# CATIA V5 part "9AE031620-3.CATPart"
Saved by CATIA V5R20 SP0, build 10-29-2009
Part number: 9AE031620-3
Revision: ANY
Definition: UNKNOWN
Nomenclature: 9AE031620-3
Source: Unknown
Bounding box of the stored display mesh (mm): x -6.55 to 12.95, y -19 to 27, z -9.75 to 9.75
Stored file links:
  C:\Users\Utente\Desktop\IO LAVORO\3D X SITO CF\CUMSA\3D files AE\AE 031620\9AE031620-3.CATPart
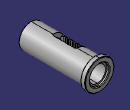
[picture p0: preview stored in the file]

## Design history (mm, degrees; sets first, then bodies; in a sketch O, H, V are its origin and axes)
Body1 "Cortar-Barrer1" (main body)
  Solid1: solid without history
